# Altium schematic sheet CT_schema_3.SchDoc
size 287 x 169 mm
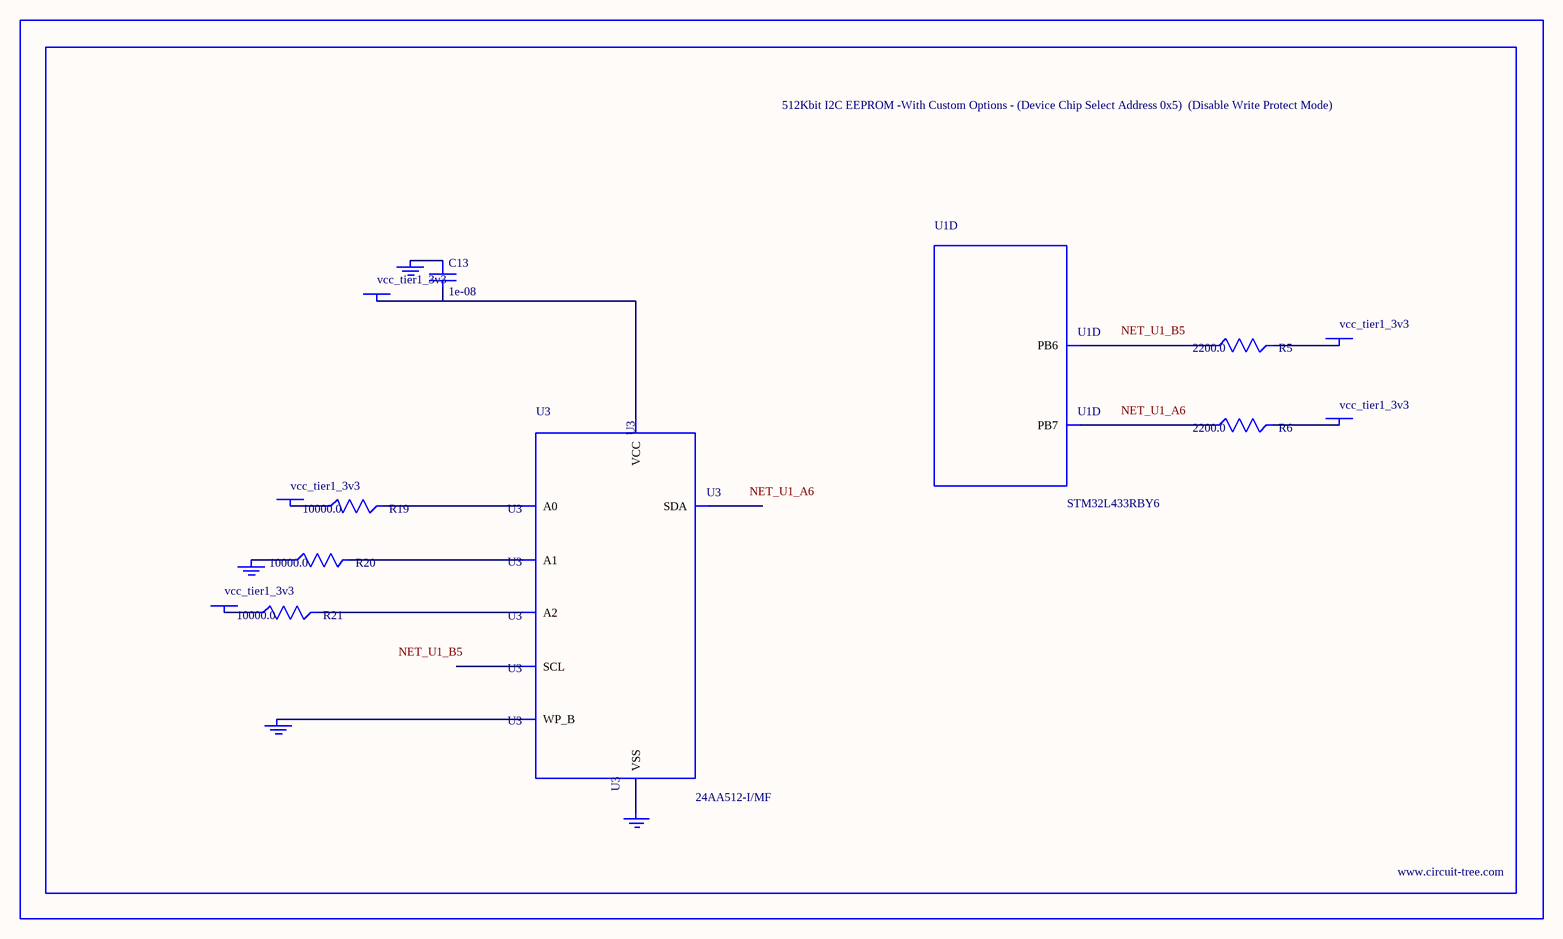
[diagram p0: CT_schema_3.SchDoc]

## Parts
BORDER2  (no value)
C13  1e-08  [C0402]
GND_INSTANCE_2_0  (no value)
GND_INSTANCE_2_1  (no value)
GND_INSTANCE_2_2  (no value)
GND_INSTANCE_2_3  (no value)
POWER_INSTANCE_2_0  vcc_tier1_3v3
POWER_INSTANCE_2_1  vcc_tier1_3v3
POWER_INSTANCE_2_2  vcc_tier1_3v3
POWER_INSTANCE_2_3  vcc_tier1_3v3
POWER_INSTANCE_2_4  vcc_tier1_3v3
R5  2200.0  [R0603]
R6  2200.0  [R0603]
R19  10000.0  [R0603]
R20  10000.0  [R0603]
R21  10000.0  [R0603]
U1  STM32L433RBY6  [WLCSP64]  (part D of 6)
U3  24AA512-I/MF  [DFN8-S]

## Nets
NetC13_1: C13.1 GND_INSTANCE_2_2.0(GND)
NetC13_2: C13.2 POWER_INSTANCE_2_2.0(PWR) U3.8(VCC)
NetGND_INSTANCE_2_0_0: GND_INSTANCE_2_0.0(GND) R20.1
NetGND_INSTANCE_2_1_0: GND_INSTANCE_2_1.0(GND) U3.7(WP_B)
NetGND_INSTANCE_2_3_0: GND_INSTANCE_2_3.0(GND) U3.4(VSS)
NetPOWER_INSTANCE_2_0_0: POWER_INSTANCE_2_0.0(PWR) R19.1
NetPOWER_INSTANCE_2_1_0: POWER_INSTANCE_2_1.0(PWR) R21.1
NetPOWER_INSTANCE_2_3_0: POWER_INSTANCE_2_3.0(PWR) R5.2
NetPOWER_INSTANCE_2_4_0: POWER_INSTANCE_2_4.0(PWR) R6.2
NetR5_1: R5.1 U1.B5(PB6)
NetR6_1: R6.1 U1.A6(PB7)
NetR19_2: R19.2 U3.1(A0)
NetR20_2: R20.2 U3.2(A1)
NetR21_2: R21.2 U3.3(A2)

Not connected (* = marked no-connect by the designer): U3 5(SDA) 6(SCL)

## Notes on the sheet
- Labels drawn without touching a wire or pin: NET_U1_A6, NET_U1_B5

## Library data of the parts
BORDER2 = BORDER_PAGE2
C13 = C0402C103K3RAC
GND_INSTANCE_2_0-GND_INSTANCE_2_3 = GND
POWER_INSTANCE_2_0-POWER_INSTANCE_2_4 = PWR
R5 R6 = RC0603JR-072K2L
R19-R21 = RC0603JR-0710KL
